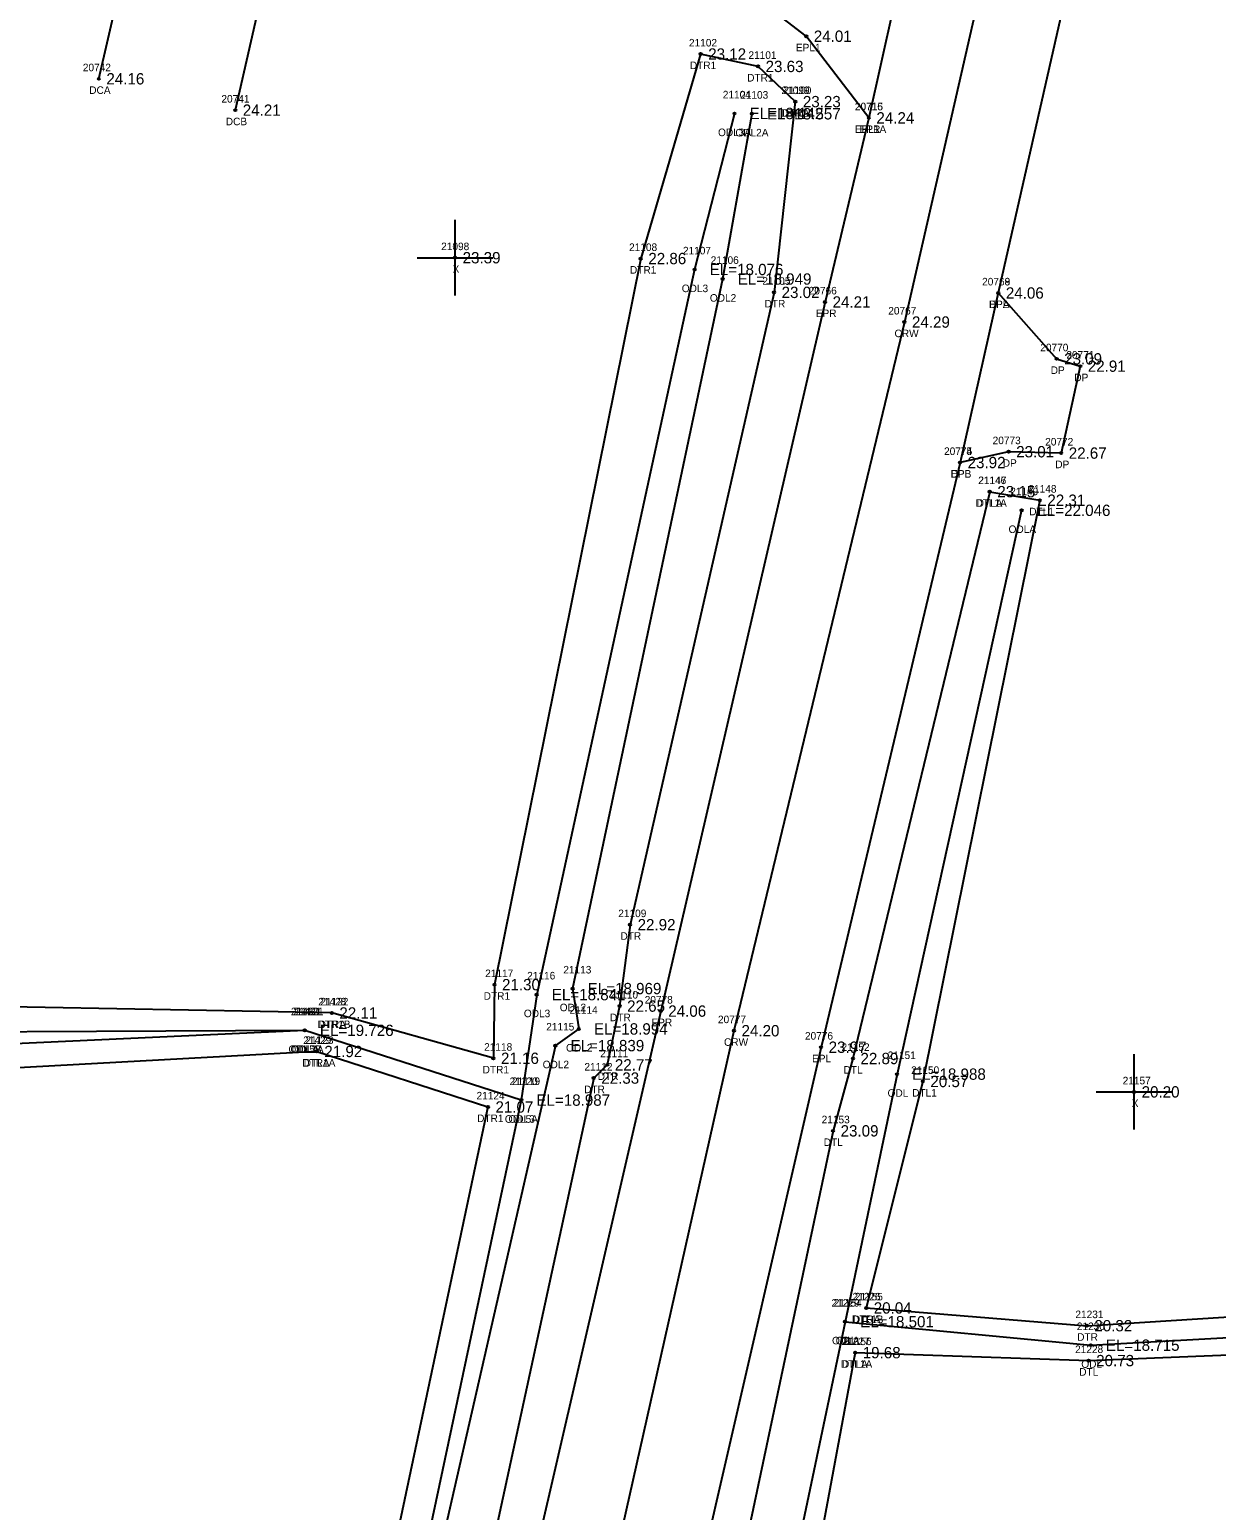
# Model space of a CAD drawing. Extents: x 2655177 to 2656219, y 761780 to 764748.
# Drawn here: x 2655348.9 to 2655506.1, y 761983.8 to 762179.8 of the extents above; entities that cross this region are included whole.
import ezdxf

# ---------------------------------------------------------------- set-up
doc = ezdxf.new("R2010")
doc.units = 0
for name, color, linetype in [('RD_DTM_BkLn1', 7, 'Continuous'), ('RD_EX_Conc', 7, 'Continuous'), ('RD_EX_Conc_txCode', 7, 'Continuous'), ('RD_EX_Driveway', 7, 'Continuous'), ('RD_EX_Driveway_txCode', 7, 'Continuous'), ('RD_EX_H2O', 7, 'Continuous'), ('RD_EX_H2O_txCode', 7, 'Continuous'), ('RD_EX_Misc', 7, 'Continuous'), ('RD_EX_Misc_txCode', 7, 'Continuous'), ('RD_EX_Road', 7, 'Continuous'), ('RD_EX_Road_txCode', 7, 'Continuous'), ('RD_EX_TX_Conc_ELEV', 7, 'Continuous'), ('RD_EX_TX_Driveway_ELEV', 7, 'Continuous'), ('RD_EX_TX_H2O_ELEV', 7, 'Continuous'), ('RD_EX_TX_Misc_ELEV', 7, 'Continuous'), ('RD_EX_TX_Road_ELEV', 7, 'Continuous'), ('RD_HC_Survey_ELEV', 7, 'Continuous'), ('RD_HC_Survey_txCode', 7, 'Continuous'), ('RD_SMD_Locator', 7, 'Continuous')]:
    doc.layers.add(name, color=color, linetype=linetype)

msp = doc.modelspace()

# ---------------------------------------------------------------- linework, layer by layer
at = {"layer": 'RD_DTM_BkLn1'}
msp.add_lwpolyline([(2655711.06, 763230.3), (2655703.38, 763195.9), (2655681.97, 763099.65), (2655659.44, 762998.39), (2655637.72, 762903.26), (2655615.94, 762806.28), (2655593.94, 762710.45), (2655572.67, 762616.37), (2655551.12, 762519.58), (2655528.83, 762422.13), (2655507.58, 762326.81), (2655486.01, 762234.2), (2655464.77, 762141.12), (2655442.2, 762047.28), (2655420.99, 761952.95), (2655398.79, 761855.74), (2655384.11, 761791.21)], dxfattribs=at)
at = {"layer": 'RD_EX_Conc'}
for points in [[(2655358.1, 762173.33), (2655364.42, 762200.63), (2655364.75, 762204.3), (2655363.82, 762207.54)], [(2655385.4, 762200.51), (2655383.54, 762198.77), (2655382.39, 762196.49), (2655376.16, 762169.18)]]:
    msp.add_lwpolyline(points, dxfattribs=at)
at = {"layer": 'RD_EX_Driveway'}
msp.add_lwpolyline([(2655477.2, 762144.97), (2655484.92, 762136.25), (2655488.05, 762135.28), (2655485.53, 762123.77), (2655478.57, 762123.95), (2655472.14, 762122.52)], dxfattribs=at)
at = {"layer": 'RD_EX_H2O'}
msp.add_line((2655414.04, 762038.09), (2655385.37, 762047.33), dxfattribs=at)
for points in [[(2655458.25, 762004.65), (2655489.16, 762003.6), (2655538.42, 762005.59), (2655556.05, 762013.17), (2655587.88, 762051.39), (2655643.4, 762074.04), (2655655.85, 762091.76), (2655681.86, 762140.14), (2655683.72, 762146.53), (2655664.39, 762201.23), (2655621.98, 762271.36), (2655558.86, 762321.08)], [(2655459.71, 762010.57), (2655488.92, 762008.22), (2655537.08, 762011.25), (2655554.9, 762018.55), (2655583.72, 762054.68), (2655639.44, 762078.76), (2655651.66, 762094.07), (2655673.82, 762140.27), (2655676.22, 762150.22), (2655658.16, 762196.88), (2655618.83, 762267.48), (2655556.47, 762317.07), (2655558.86, 762321.08)], [(2655456.91, 762008.75), (2655489.44, 762005.64), (2655537.92, 762008.34), (2655555.32, 762016.59), (2655585.73, 762052.79), (2655641.23, 762076.72), (2655654.31, 762091.55), (2655679.19, 762140.68), (2655679.13, 762150.47), (2655660.06, 762199), (2655620.4, 762269.42), (2655559.84, 762317.9)], [(2655450.32, 762170.31), (2655445.39, 762174.97), (2655437.79, 762176.61), (2655429.86, 762149.53), (2655410.49, 762053.38), (2655410.35, 762043.63), (2655388.95, 762049.63)], [(2655450.32, 762170.31), (2655447.51, 762145.05), (2655428.44, 762061.32), (2655427.05, 762050.54), (2655425.43, 762042.76), (2655423.63, 762041.01), (2655404.09, 761950.81), (2655382.1, 761859.05), (2655367.49, 761795.82)], [(2655442.27, 762168.74), (2655436.99, 762148.08), (2655416.08, 762052.07), (2655414.04, 762038.09), (2655395.9, 761952.78), (2655372.72, 761860.9), (2655355.36, 761798.35)], [(2655444.57, 762168.7), (2655440.7, 762146.82), (2655420.83, 762052.86), (2655421.66, 762047.52), (2655418.56, 762045.31), (2655397.35, 761952.35), (2655376.67, 761860.25), (2655360.51, 761796.78)], [(2655476.07, 762118.66), (2655457.95, 762043.6), (2655455.32, 762034.02), (2655437.36, 761949.13), (2655416.41, 761851.26), (2655413.59, 761836.57), (2655406.69, 761818.38), (2655416.71, 761813.93)], [(2655476.07, 762118.66), (2655482.7, 762117.53), (2655467.21, 762040.56), (2655459.71, 762010.57)], [(2655480.29, 762116.19), (2655463.79, 762041.53), (2655456.91, 762008.75), (2655444.17, 761948.07), (2655421.03, 761850.25), (2655417.22, 761835.53), (2655412.59, 761818.61)], [(2655388.95, 762049.63), (2655313, 762051.05), (2655289.65, 762056.26), (2655236.79, 762050.02), (2655233.87, 762053.67)], [(2655386.96, 762044.53), (2655311.1, 762040.37), (2655293.44, 762044.27), (2655237.39, 762043.26), (2655233.87, 762053.67)], [(2655385.37, 762047.33), (2655311.4, 762043.92), (2655291.93, 762049.03), (2655236.95, 762048.24), (2655233.87, 762053.67)], [(2655385.37, 762047.33), (2655311.74, 762046.95), (2655290.92, 762052.49), (2655236.95, 762048.24)], [(2655386.96, 762044.53), (2655409.62, 762037.18), (2655391.92, 761953.74), (2655368.61, 761861.23), (2655351.84, 761799.36)], [(2655458.25, 762004.65), (2655447.62, 761947.28), (2655424.45, 761849.54), (2655416.71, 761813.93)]]:
    msp.add_lwpolyline(points, dxfattribs=at)
at = {"layer": 'RD_EX_Misc'}
for p, q in [((2655405.27, 762144.64), (2655405.27, 762154.64)), ((2655400.27, 762149.64), (2655410.27, 762149.64)), ((2655495.18, 762034.18), (2655495.18, 762044.18)), ((2655490.18, 762039.18), (2655500.18, 762039.18))]:
    msp.add_line(p, q, dxfattribs=at)
at = {"layer": 'RD_EX_Road'}
for points in [[(2655700.99, 763232.28), (2655693.55, 763198.57), (2655671.65, 763102.04), (2655649.04, 763001.06), (2655627.27, 762906.23), (2655605, 762809.37), (2655598.99, 762783.09), (2655583.65, 762714.14), (2655561.97, 762618.32), (2655556.36, 762593.84), (2655548.11, 762557.14), (2655540.1, 762522.48), (2655518.03, 762425.04), (2655496.48, 762329.56), (2655475.55, 762236.62), (2655473.2, 762226.14), (2655466.57, 762197.5), (2655460.06, 762168.16), (2655454.26, 762143.78), (2655432.5, 762049.88), (2655410.7, 761955.51), (2655388.17, 761858.43), (2655373.5, 761793.95)], [(2655576.46, 762583.32), (2655561.41, 762517.24), (2655539.15, 762414.81), (2655531.98, 762386.15), (2655517.98, 762324.29), (2655508.17, 762280.15), (2655501.46, 762251.6), (2655496.92, 762232.09), (2655477.2, 762144.97), (2655472.14, 762122.52), (2655453.74, 762045.1), (2655431.79, 761949.92), (2655409.76, 761853.25), (2655401.25, 761816.42), (2655394.61, 761787.37)], [(2655460.06, 762168.16), (2655451.77, 762178.97), (2655440.54, 762187.62)]]:
    msp.add_lwpolyline(points, dxfattribs=at)
at = {"layer": 'RD_SMD_Locator'}
for centre in [(2655451.77, 762178.97), (2655437.79, 762176.61), (2655445.39, 762174.97), (2655358.1, 762173.33), (2655376.16, 762169.18), (2655450.32, 762170.31), (2655450.32, 762170.31), (2655442.27, 762168.74), (2655444.57, 762168.7), (2655460.06, 762168.16), (2655460.06, 762168.16), (2655405.27, 762149.64), (2655429.86, 762149.53), (2655436.99, 762148.08), (2655440.7, 762146.82), (2655447.51, 762145.05), (2655454.26, 762143.78), (2655477.2, 762144.97), (2655477.2, 762144.97), (2655464.77, 762141.12), (2655484.92, 762136.25), (2655488.05, 762135.28), (2655478.57, 762123.95), (2655472.14, 762122.52), (2655472.14, 762122.52), (2655485.53, 762123.77), (2655476.07, 762118.66), (2655476.07, 762118.66), (2655480.29, 762116.19), (2655482.7, 762117.53), (2655428.44, 762061.32), (2655410.49, 762053.38), (2655416.08, 762052.07), (2655420.83, 762052.86), (2655388.95, 762049.63), (2655388.95, 762049.63), (2655427.05, 762050.54), (2655432.5, 762049.88), (2655421.66, 762047.52), (2655385.37, 762047.33), (2655385.37, 762047.33), (2655385.37, 762047.33), (2655442.2, 762047.28), (2655386.96, 762044.53), (2655386.96, 762044.53), (2655410.35, 762043.63), (2655418.56, 762045.31), (2655453.74, 762045.1), (2655457.95, 762043.6), (2655425.43, 762042.76), (2655463.79, 762041.53), (2655423.63, 762041.01), (2655467.21, 762040.56), (2655414.04, 762038.09), (2655414.04, 762038.09), (2655495.18, 762039.18), (2655409.62, 762037.18), (2655455.32, 762034.02), (2655459.71, 762010.57), (2655459.71, 762010.57), (2655456.91, 762008.75), (2655456.91, 762008.75), (2655488.92, 762008.22), (2655458.25, 762004.65), (2655458.25, 762004.65), (2655489.44, 762005.64), (2655489.16, 762003.6)]:
    msp.add_circle(centre, 0.15, dxfattribs=at)

# ---------------------------------------------------------------- texts
at = {"layer": 'RD_EX_Conc_txCode'}
for s, p in [('20742', (2655355.98, 762174.33)), ('DCA', (2655356.83, 762171.33)), ('20741', (2655374.33, 762170.18)), ('DCB', (2655374.91, 762167.18))]:
    msp.add_text(s, height=1, dxfattribs=at).set_placement(p)
at = {"layer": 'RD_EX_Driveway_txCode'}
for s, p in [('20769', (2655475.06, 762145.97)), ('DPA', (2655475.94, 762142.97)), ('20770', (2655482.76, 762137.25)), ('20771', (2655486.21, 762136.28)), ('DP', (2655484.14, 762134.25)), ('DP', (2655487.27, 762133.28)), ('20773', (2655476.45, 762124.95)), ('20774', (2655470.02, 762123.52)), ('20772', (2655483.41, 762124.77)), ('DP', (2655477.79, 762121.95)), ('DP', (2655484.75, 762121.77)), ('DPB', (2655470.89, 762120.52))]:
    msp.add_text(s, height=1, dxfattribs=at).set_placement(p)
at = {"layer": 'RD_EX_H2O_txCode'}
for s, p in [('21102', (2655436.24, 762177.61)), ('21101', (2655444.12, 762175.97)), ('DTR1', (2655436.36, 762174.61)), ('DTR1', (2655443.95, 762172.97)), ('21104', (2655440.72, 762170.74)), ('21103', (2655443.02, 762170.7)), ('21099', (2655448.49, 762171.31)), ('21100', (2655448.73, 762171.31)), ('DTR1A', (2655448.4, 762168.31)), ('DTRA', (2655448.57, 762168.31)), ('ODL3A', (2655440.09, 762165.74)), ('ODL2A', (2655442.39, 762165.7)), ('21108', (2655428.31, 762150.53)), ('21107', (2655435.44, 762150.08)), ('21106', (2655439.12, 762148.82)), ('DTR1', (2655428.43, 762147.53)), ('ODL3', (2655435.29, 762145.08)), ('21105', (2655445.96, 762146.05)), ('ODL2', (2655439.01, 762143.82)), ('DTR', (2655446.25, 762143.05)), ('21146', (2655474.53, 762119.66)), ('21147', (2655474.56, 762119.66)), ('21149', (2655478.78, 762118.19)), ('21148', (2655481.19, 762118.53)), ('DTL1A', (2655474.17, 762116.66)), ('DTLA', (2655474.34, 762116.66)), ('DTL1', (2655481.3, 762115.53)), ('ODLA', (2655478.56, 762113.19)), ('21109', (2655426.88, 762062.32)), ('DTR', (2655427.17, 762059.32)), ('21117', (2655409.26, 762054.38)), ('21113', (2655419.6, 762054.86)), ('21116', (2655414.82, 762054.07)), ('21428', (2655387.15, 762050.63)), ('21122', (2655387.43, 762050.63)), ('DTR1', (2655409.06, 762051.38)), ('21110', (2655425.78, 762051.54)), ('21430', (2655383.54, 762049.33)), ('21431', (2655383.86, 762049.33)), ('21121', (2655384.15, 762049.33)), ('ODL3', (2655414.38, 762049.07)), ('ODL2', (2655419.13, 762049.86)), ('21114', (2655420.43, 762049.52)), ('DTR', (2655425.78, 762048.54)), ('DTR1B', (2655387.04, 762047.63)), ('DTRA', (2655387.19, 762047.63)), ('21115', (2655417.34, 762047.31)), ('21429', (2655385.16, 762045.53)), ('21123', (2655385.45, 762045.53)), ('21118', (2655409.12, 762044.63)), ('21152', (2655456.44, 762044.6)), ('ODL5B', (2655383.21, 762044.33)), ('ODL1A', (2655383.48, 762044.33)), ('ODLA', (2655383.64, 762044.33)), ('ODL2', (2655419.96, 762044.52)), ('21111', (2655424.49, 762043.76)), ('21151', (2655462.56, 762043.53)), ('DTR1A', (2655385.04, 762042.53)), ('DTLA', (2655385.23, 762042.53)), ('DTR1', (2655408.92, 762041.63)), ('ODL2', (2655416.87, 762042.31)), ('21112', (2655422.4, 762042.01)), ('DTR', (2655424.16, 762040.76)), ('DTL', (2655456.71, 762041.6)), ('21150', (2655465.66, 762041.56)), ('21120', (2655412.49, 762040.09)), ('21119', (2655412.81, 762040.09)), ('DTR', (2655422.36, 762039.01)), ('21124', (2655408.11, 762038.18)), ('ODL', (2655462.54, 762038.53)), ('DTL1', (2655465.8, 762038.56)), ('DTR1', (2655408.19, 762035.18)), ('ODL5A', (2655411.86, 762035.09)), ('ODL3', (2655412.34, 762035.09)), ('21153', (2655453.81, 762035.02)), ('DTL', (2655454.08, 762032.02)), ('21226', (2655457.89, 762011.57)), ('21155', (2655458.2, 762011.57)), ('21229', (2655455.12, 762010.75)), ('21154', (2655455.4, 762010.75)), ('DTL1B', (2655457.83, 762008.57)), ('DTRA', (2655457.95, 762008.57)), ('21231', (2655487.41, 762009.22)), ('21230', (2655487.6, 762007.64)), ('ODLA', (2655455.18, 762005.75)), ('ODL', (2655455.67, 762005.75)), ('21227', (2655456.45, 762005.65)), ('21156', (2655456.71, 762005.65)), ('DTR', (2655487.65, 762006.22)), ('21228', (2655487.37, 762004.6)), ('DTL1A', (2655456.35, 762002.65)), ('DTLA', (2655456.51, 762002.65)), ('DTL', (2655487.92, 762001.6)), ('ODL', (2655488.19, 762002.64))]:
    msp.add_text(s, height=1, dxfattribs=at).set_placement(p)
at = {"layer": 'RD_EX_Misc_txCode'}
for s, p in [('21098', (2655403.43, 762150.64)), ('X', (2655404.95, 762147.64)), ('21157', (2655493.67, 762040.18)), ('X', (2655494.87, 762037.18))]:
    msp.add_text(s, height=1, dxfattribs=at).set_placement(p)
at = {"layer": 'RD_EX_Road_txCode'}
for s, p in [('EPL1', (2655450.4, 762176.97)), ('20716', (2655458.2, 762169.16)), ('20715', (2655458.22, 762169.16)), ('EPL1A', (2655458.2, 762166.16)), ('EPR', (2655458.83, 762166.16)), ('20766', (2655452.1, 762144.78)), ('20768', (2655475.06, 762145.97)), ('EPL', (2655476, 762142.97)), ('EPR', (2655453.03, 762141.78)), ('20775', (2655470.02, 762123.52)), ('EPL', (2655470.93, 762120.52)), ('20778', (2655430.38, 762050.88)), ('EPR', (2655431.27, 762047.88)), ('20776', (2655451.6, 762046.1)), ('EPL', (2655452.54, 762043.1))]:
    msp.add_text(s, height=1, dxfattribs=at).set_placement(p)
at = {"layer": 'RD_EX_TX_Conc_ELEV'}
for s, p in [('24.16', (2655359.1, 762172.58)), ('24.21', (2655377.16, 762168.43))]:
    msp.add_text(s, height=1.5, dxfattribs=at).set_placement(p)
at = {"layer": 'RD_EX_TX_Driveway_ELEV'}
for s, p in [('24.06', (2655478.2, 762144.22)), ('23.09', (2655485.92, 762135.5)), ('22.91', (2655489.05, 762134.53)), ('23.01', (2655479.57, 762123.2)), ('22.67', (2655486.53, 762123.02)), ('23.92', (2655473.14, 762121.77))]:
    msp.add_text(s, height=1.5, dxfattribs=at).set_placement(p)
at = {"layer": 'RD_EX_TX_H2O_ELEV'}
for s, p in [('23.12', (2655438.79, 762175.86)), ('23.63', (2655446.39, 762174.22)), ('23.23', (2655451.32, 762169.56)), ('23.23', (2655451.32, 762169.56)), ('EL=18.142', (2655444.27, 762167.99)), ('EL=18.557', (2655446.57, 762167.95)), ('22.86', (2655430.86, 762148.78)), ('EL=18.076', (2655438.99, 762147.33)), ('EL=18.949', (2655442.7, 762146.07)), ('23.02', (2655448.51, 762144.3)), ('23.15', (2655477.07, 762117.91)), ('23.15', (2655477.07, 762117.91)), ('22.31', (2655483.7, 762116.78)), ('EL=22.046', (2655482.29, 762115.44)), ('22.92', (2655429.44, 762060.57)), ('21.30', (2655411.49, 762052.63)), ('EL=18.969', (2655422.83, 762052.11)), ('EL=18.841', (2655418.08, 762051.32)), ('22.11', (2655389.95, 762048.88)), ('22.11', (2655389.95, 762048.88)), ('22.65', (2655428.05, 762049.79)), ('EL=19.726', (2655387.37, 762046.58)), ('EL=19.726', (2655387.37, 762046.58)), ('EL=19.726', (2655387.37, 762046.58)), ('EL=18.994', (2655423.66, 762046.77)), ('EL=18.839', (2655420.56, 762044.56)), ('21.92', (2655387.96, 762043.78)), ('21.92', (2655387.96, 762043.78)), ('21.16', (2655411.35, 762042.88)), ('22.89', (2655458.95, 762042.85)), ('22.33', (2655424.63, 762040.26)), ('22.77', (2655426.43, 762042.01)), ('EL=18.988', (2655465.79, 762040.78)), ('20.57', (2655468.21, 762039.81)), ('21.07', (2655410.62, 762036.43)), ('EL=18.987', (2655416.04, 762037.34)), ('EL=18.987', (2655416.04, 762037.34)), ('23.09', (2655456.32, 762033.27)), ('20.04', (2655460.71, 762009.82)), ('20.04', (2655460.71, 762009.82)), ('EL=18.501', (2655458.91, 762008)), ('EL=18.501', (2655458.91, 762008)), ('20.32', (2655489.92, 762007.47)), ('EL=18.715', (2655491.44, 762004.89)), ('19.68', (2655459.25, 762003.9)), ('19.68', (2655459.25, 762003.9)), ('20.73', (2655490.16, 762002.85))]:
    msp.add_text(s, height=1.5, dxfattribs=at).set_placement(p)
at = {"layer": 'RD_EX_TX_Misc_ELEV'}
for s, p in [('23.39', (2655406.27, 762148.89)), ('20.20', (2655496.18, 762038.43))]:
    msp.add_text(s, height=1.5, dxfattribs=at).set_placement(p)
at = {"layer": 'RD_EX_TX_Road_ELEV'}
for s, p in [('24.01', (2655452.77, 762178.22)), ('24.24', (2655461.06, 762167.41)), ('24.24', (2655461.06, 762167.41)), ('24.06', (2655478.2, 762144.22)), ('24.21', (2655455.26, 762143.03)), ('23.92', (2655473.14, 762121.77)), ('24.06', (2655433.5, 762049.13)), ('23.97', (2655454.74, 762044.35))]:
    msp.add_text(s, height=1.5, dxfattribs=at).set_placement(p)
at = {"layer": 'RD_HC_Survey_ELEV'}
for s, p in [('24.29', (2655465.77, 762140.37)), ('24.20', (2655443.2, 762046.53))]:
    msp.add_text(s, height=1.5, dxfattribs=at).set_placement(p)
at = {"layer": 'RD_HC_Survey_txCode'}
for s, p in [('20767', (2655462.63, 762142.12)), ('CRW', (2655463.46, 762139.12)), ('20777', (2655440.08, 762048.28)), ('CRW', (2655440.88, 762045.28))]:
    msp.add_text(s, height=1, dxfattribs=at).set_placement(p)

doc.saveas('drawing.dxf')
